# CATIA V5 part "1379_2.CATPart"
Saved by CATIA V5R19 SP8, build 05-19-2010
Part number: 2
Bounding box of the stored display mesh (mm): x -10 to 10, y -11 to 51.5, z 35.5 to 71.5
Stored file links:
  C:\Users\ThinkMotion\Desktop\EU_thinkMotion\iao\IAO_MMS_Groupe3\bblot\bblot\1379_2.CATPart
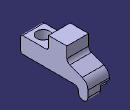
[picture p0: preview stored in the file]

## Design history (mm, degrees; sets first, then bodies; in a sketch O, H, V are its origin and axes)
Body1 (main body)
  Point1: stored without definition
  Sketch1 on yz-plane, origin (0, 0, 0), H (0, 1, 0), V (0, 0, 1)
    point P1 (-11, 59.5)
    line L1 (-11, 57.5) -> (-11, 46.5)
    line L2 (-9, 44.5) -> (39.5, 44.5)
    line L3 (42.5, 41.5) -> (42.5, 40)
    line L4 (51.5, 40) -> (51.5, 46.0001)
    line L5 (46.2362, 53.5176) -> (34.6319, 57.7412)
    line L6 (32, 61.5) -> (32, 71.5)
    line L7 (32, 71.5) -> (15, 71.5)
    line L8 (15, 71.5) -> (15, 61.5)
    line L9 (13, 59.5) -> (-9, 59.5)
    point P6 (-11, 59.5)
    arc A1 centre (47, 40) radius 4.5 from (42.5, 40) to (51.5, 40) ccw
    point P7 (47, 40)
    reference projected point E1 (47, 40) from Point1
    arc A2 centre (-9, 46.5) radius 2 from (-11, 46.5) to (-9, 44.5) ccw
    arc A3 centre (-9, 57.5) radius 2 from (-11, 57.5) to (-9, 59.5) cw
    arc A4 centre (39.5, 41.5) radius 3 from (39.5, 44.5) to (42.5, 41.5) cw
    arc A5 centre (13, 61.5) radius 2 from (15, 61.5) to (13, 59.5) cw
    arc A6 centre (36, 61.5) radius 4 from (34.6319, 57.7412) to (32, 61.5) cw
    arc A7 centre (43.5, 46.0001) radius 8 from (51.5, 46.0001) to (46.2362, 53.5176) ccw
    reference projected line E2 through (0, 0) direction (0, 1) from Line2
    construction circle A8 centre (47, 40) radius 4.5
    reference projected line E3 through (0, 0) direction (0, -1) from edge of DatumCurve1
    axis line L10 (32, 61.5) -> (15, 61.5)
    radius A2 = 2
    radius A3 = 2
    radius A4 = 3
    radius A5 = 2
    radius A6 = 4
    radius A7 = 8
    distance L4 L3 = 9
    distance L9 L2 = 15
    distance E2 L1 = 11
    distance E3 L8 = 15
    length L7 = 17
    length L8 = 10
    angle L5 L6 = 110
    vertical: L1 V, L3 V, L4 V, L6 V, L8 V
    horizontal: L2 H, L7 H, L9 H, L10 H
    coincidence: P6 L1, P1 P6, P7 E1, L1 P1, L9 P6
    tangency: A1 L3, A1 L4, A2 L1, A2 L2, A3 L1, A3 L9, A4 L2, A4 L3, A5 L8, A5 L9, A6 L5, A6 L6, A7 L4, A7 L5, A8 L4, L2 A8
  Pad1: profile Sketch1, direction (1, 0, 0), length 10, opposite side length 10
  Sketch2 on face of Pad1 from Sketch1.L9, origin (-0.8575, -5.5839, 59.5), H (1, 0, 0), V (0, 1, 0)
    point P1 (0.8575, 5.5839)
    reference projected point E1 (0.8575, 5.5839) from Line1
    coincidence: P1 E1
  Hole1: placed by Sketch2, at (0, 0, 59.5) direction (0, 0, -1), diameter 12, through (limit type 3)
  Plane1: stored without definition
  Sketch3 on start face of Pad1, origin (-10, 0, 0), H (0, -1, 0), V (0, 0, 1)
    line L1 (-51.5, 44.5) -> (11, 44.5)
    point P2 (-51.5, 44.5)
    reference projected line E1 (-51.5, 40) -> (-51.5, 62.9064) from edge [start face of Pad1 | face of Pad1 from Sketch1.L4]
    line L2 (11, 44.5) -> (11, 35.5)
    point P4 (11, 35.5)
    line L3 (-51.5, 44.5) -> (-51.5, 35.5)
    point P5 (-51.5, 35.5)
    point P6 (-51.5, 35.5)
    construction circle A1 centre (-47, 40) radius 4.5
    circle A2 centre (-47, 40) radius 1.5
    reference projected line E2 (-51.5, 40) -> (-51.5, 46.0001) from edge [start face of Pad1 | face of Pad1 from Sketch1.L4]
    reference projected arc E3 centre (-47, 40) radius 4.5 from (-51.5, 40) to (-42.5, 40) ccw from edge [start face of Pad1 | face of Pad1 from Sketch1.A1]
    line L4 (-51.5, 35.5) -> (11, 35.5)
    point P7 (11, 35.5)
    reference projected line E4 (11, 57.5) -> (11, 46.5) from edge [start face of Pad1 | face of Pad1 from Sketch1.L1]
    radius A2 = 1.5
    horizontal: L1 H, L4 H
    coincidence: P2 E1, L3 P6, P5 P6, L3 E2, A1 E3, P7 L2, P4 P7, E4 L2
    vertical: L2 V
    tangency: L1 A1, A1 L4
  Pocket1: profile Sketch3, direction (1, 0, 0), up to Plane1
  Line1: stored without definition
  Line2: stored without definition
  DatumCurve1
